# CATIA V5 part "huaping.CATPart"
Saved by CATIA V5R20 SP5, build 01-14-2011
Part number: 花瓶
Material "DS star": density 1000 kg/m3
Material "Fire Red": density 7860 kg/m3, Young's modulus 2e+11 Pa, Poisson ratio 0.266
Material "Slightly Cloudy"
Bounding box of the stored display mesh (mm): x -29.95 to 29.95, y -30.087 to 29.92, z 0 to 116.08
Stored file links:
  E:\dzy\huaping.CATPart
  C:\Program Files\Dassault Systemes\B20\intel_a\startup\materials\Catalog.CATMaterial
  C:\Program Files\Dassault Systemes\B20\intel_a\startup\materials\yellow_env_512x512.jpg
  C:\Program Files\Dassault Systemes\B20\intel_a\startup\materials\DS_star.jpg
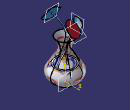
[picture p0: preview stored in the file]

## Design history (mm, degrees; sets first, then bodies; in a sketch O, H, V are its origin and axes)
Set1
  Plane1: type Offset, RefPlane xy-plane, Offset 20
  Plane2: type Offset, RefPlane Plane1, Offset 20
  Plane3: type Offset, RefPlane Plane2, Offset 20
  Plane4: type Offset, RefPlane Plane3, Offset 20
  Sketch1 on xy-plane, origin (0, 0, 0), H (1, 0, 0), V (0, 1, 0)
    circle A1 centre (0, 0) radius 15
    point P1 (15, 0)
    radius A1 = 15
    coincidence: A1 P1, P1 H
  Sketch2 on Plane1, origin (0, 0, 20), H (1, 0, 0), V (0, 1, 0)
    circle A1 centre (0, 0) radius 30
    point P1 (30, 0)
    radius A1 = 30
    coincidence: A1 P1, P1 H
  Sketch3 on Plane2, origin (0, 0, 40), H (1, 0, 0), V (0, 1, 0)
    circle A1 centre (0, 0) radius 20
    radius A1 = 20
  Sketch4 on Plane3, origin (0, 0, 60), H (1, 0, 0), V (0, 1, 0)
    circle A1 centre (0, 0) radius 10
    radius A1 = 10
  Sketch5 on Plane4, origin (0, 0, 80), H (1, 0, 0), V (0, 1, 0)
    circle A1 centre (0, 0) radius 17.5
    radius A1 = 17.5
Body1 (main body), material "DS star"
  Loft1: solid, Sections (Sketch1; Sketch2; Sketch3; Sketch4; Sketch5)
  Shell1: ExtOffset 0, Face face of Loft1, IntOffset 1
  Sketch6 on yz-plane, origin (0, 0, 0), H (0, 1, 0), V (0, 0, 1)
    axis line L1 (0, 30) -> (0, -10)
    point P1 (0, 30)
    spline S1 through (0, 0) (0, 30)
    line L2 (0, 30) -> (20.3139, 30)
    point P3 (20.3139, 30)
    spline S2 through (20.3139, 30) (25.022, 20.1953) (12.3588, 0)
    line L3 (0, 0) -> (12.3588, 0)
    point P4 (12.3588, 0)
    point P5 (12.3588, 0)
    point P6 (0, 0)
    point P7 (0, 30)
    point P8 (20.3139, 30)
    coincidence: P5 P4, O P6, P1 P7, P3 P8
  Shaft1: profile Sketch6, axis Sketch6.L1, angle 360
Body2
  Sketch7 on yz-plane, origin (0, 0, 0), H (0, 1, 0), V (0, 0, 1)
    axis line L1 (0, 31.0731) -> (0, -6.1715)
    point P1 (0, 31.0731)
    line L2 (0, 0) -> (0, 32.6924)
    line L3 (0, 32.6924) -> (17.2769, 32.6924)
    line L4 (17.2769, 32.6924) -> (20.2301, 32.6924)
    arc A1 centre (6.1024, 18.8292) radius 19.7934 from (20.2301, 32.6924) to (15.6602, 1.4963) cw
    line L5 (15.6602, 1.4963) -> (13.4127, 0.257)
    line L6 (13.4127, 0.257) -> (0, 0)
    coincidence: P1 V, A1 O
    vertical: L1 V, L2 V
    horizontal: L3 H, L4 H
    tangency: L5 A1
  Shaft2: profile Sketch7, axis Sketch7.V, angle 360
  Sketch8 on yz-plane, origin (0, 0, 0), H (0, 1, 0), V (0, 0, 1)
    construction line L1 (0, 110) -> (0, -15.8449)
    point P1 (0, 110)
    axis line L2 (0, 92.1304) -> (0, -9.8167)
    point P3 (0, 92.1304)
    coincidence: P1 V, P3 L1
    vertical: L1 V, L2 V
Body3, material "Fire Red"
  Sketch9 on yz-plane, origin (0, 0, 0), H (0, 1, 0), V (0, 0, 1)
    spline S1 through (15.0908, 11.2485) (3.236, 60.5232) (21.4742, 95.6155)
  Plane5: type Normal, Curve Sketch9, RefPoint vertex of Sketch9
  Circle1: type CtrRad, Start 0, End 180, Radius 1, Center vertex of Sketch9, Support Plane5, FirstDirection (1, 0, 0)
  Rib1: profile Circle1, centre curve Sketch9
  Sketch10 on Plane5, origin (0, 57.1686, 63.4597), H (1, 0, 0), V (0, -0.743, 0.6693)
    spline S1 through (0, 39.7064) (9.9714, 46.2026) (0, 69.8374) (-9.7152, 51.4547) (0, 39.7064)
    point P1 (0, 39.7064)
    point P2 (0, 69.8374)
    point P3 (0, 39.7064)
    coincidence: P1 V, P2 V, P3 P1
  Pad1: profile Sketch10, direction (0, -0.6693, -0.743), length 1
Body4, material "Slightly Cloudy"
  Sketch11 on yz-plane, origin (0, 0, 0), H (0, 1, 0), V (0, 0, 1)
    spline S1 through (-2.0195, 7.295) (-8.7311, 41.286) (1.2021, 88.6593) (-27.2552, 106.3239)
  Plane6: type Normal, Curve Sketch11, RefPoint vertex of Sketch11
  Circle2: type CtrRad, Start 0, End 180, Radius 1, Center vertex of Sketch11, Support Plane6, FirstDirection (1, 0, 0)
  Rib2: profile Circle2, centre curve Sketch11
  Sketch12 on Plane6, origin (0, -44.4451, 7.7507), H (1, 0, 0), V (0, 0.1718, 0.9851)
    spline S1 through (-19.2757, 99.7828) (-10.4051, 105.6009) (0, 109.7899) (10.3706, 105.6009) (19.708, 99.7828) (10.3706, 93.2666) (0, 89.3103) (-10.4051, 93.2666) (-19.2757, 99.7828)
    point P1 (0, 109.7899)
    point P2 (0, 89.3103)
    point P3 (-19.2757, 99.7828)
    point P4 (-19.2757, 99.7828)
    coincidence: P1 V, P2 V, P3 P4
  Pad2: profile Sketch12, direction (0, -0.9851, 0.1718), length 1
  Sketch13 on zx-plane, origin (0, 0, 0), H (-1, 0, 0), V (0, 0, 1)
    spline S1 through (-6.3838, 11.0641) (-14.2895, 34.3423) (8.3245, 74.6666) (12.737, 85.4808) (24.6874, 88.7801)
  Plane7: type Normal, Curve Sketch13, RefPoint vertex of Sketch13
  Circle3: type CtrRad, Start 0, End 180, Radius 1, Center vertex of Sketch13, Support Plane7, FirstDirection (0, 1, 0)
  Rib3: profile Circle3, centre curve Sketch13
  Sketch14 on Plane7, origin (-14.0938, 0, -1.651), H (0, 1, 0), V (-0.1163, 0, 0.9932)
    spline S1 through (-5.0552, 91.5505) (-4.0573, 101.665) (8.7493, 98.183) (8.7493, 87.2394) (-13.2048, 87.2394) (-12.0406, 93.5403) (-5.0552, 91.5505)
    point P1 (-5.0552, 91.5505)
    point P2 (-5.0552, 91.5505)
    coincidence: P1 P2
  Pad3: profile Sketch14, direction (0.9932, 0, 0.1163), length 1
